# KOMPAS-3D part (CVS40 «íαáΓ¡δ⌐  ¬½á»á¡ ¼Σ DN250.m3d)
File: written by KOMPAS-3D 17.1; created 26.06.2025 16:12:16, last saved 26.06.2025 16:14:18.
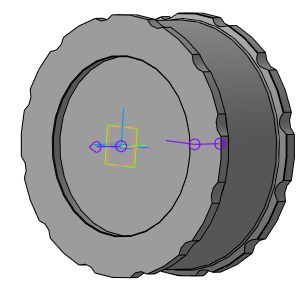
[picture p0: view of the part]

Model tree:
1. Эскиз:1
2. Элемент вращения:1
     Угол 1 = 360
3. Присоединительная точка:1
4. Присоединительная точка:2
5. Эскиз:2
6. Элемент выдавливания:1
     Расстояние 2 = 145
